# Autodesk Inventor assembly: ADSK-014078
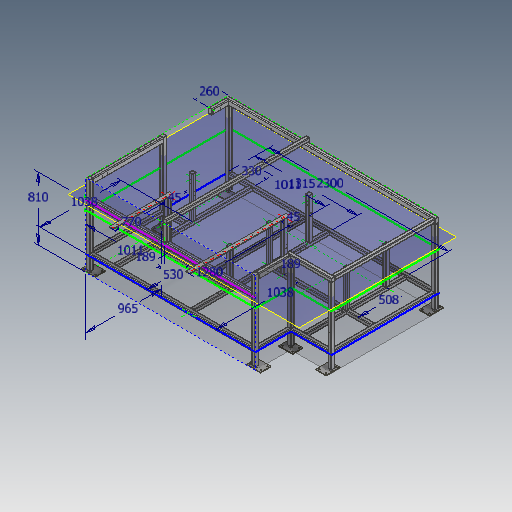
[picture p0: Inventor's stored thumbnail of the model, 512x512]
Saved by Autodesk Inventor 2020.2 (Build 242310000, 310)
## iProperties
_SolveAssemblyDoc: Frame Generator Solve Assembly
_Version: 15.0.0
Created: 2019-10
Part Number: ADSK-014078
Document SubType Name: Assembly
Designer: lutzd
Mass: 3.88702e+07 g
Surface Area: 332354 cm^2
Volume: 4.9579e+06 cm^3
Density: 7.84006 g/cm^3
VLDS_Profile: Default Assembly
VLDS_TimeStamp: 2016-07-29
VLDS_FailCnt: 0
VLDS_AcceptCnt: 0
Dimensions: 2090,9x1100x2753,9 mm
Mass: 38870,239 kg
DocNumber: ADSK-014078
Folder: 01 - Themengebiete\Simplification\01 - Packaging machine\
VDS_Category: 3D Komponenten
VDS_NumSchm: Autodesk
Title: base frame
Author: lutzd
Revision Number: -
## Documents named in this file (5)
- D:\07 - DEMODATEN\OTX 2019 - Dataset - UPDATE - Dez2019\Designs\07-Packing machine\ADSK-014078.iam
- D:\07 - DEMODATEN\OTX 2019 - Dataset - UPDATE - Dez2019\Designs\07-Packing machine\Parts\ADSK-014077.ipt
- D:\07 - DEMODATEN\OTX 2019 - Dataset - UPDATE - Dez2019\Designs\07-Packing machine\ADSK-014078\Frame\ADSK-014079.iam
- D:\07 - DEMODATEN\OTX 2019 - Dataset - UPDATE - Dez2019\Designs\07-Packing machine\Parts\ADSK-011287.ipt
- D:\07 - DEMODATEN\OTX 2019 - Dataset - UPDATE - Dez2019\Designs\07-Packing machine\Parts\ADSK-011288.ipt
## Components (16 placed, 4 different names)
1. ADSK-014077:1 — Fluchtend:5, Fluchtend:6, Fluchtend:7, Fluchtend:8, Fluchtend:9, Fluchtend:10, Fluchtend:11
2. ADSK-014079:1 [sub-assembly] — Passend:25, Passend:26, Passend:44, Passend:51, Passend:52, Passend:53, Passend:60, Passend:61, Passend:68, Passend:69
3. ADSK-011287:5 — Passend:37, Passend:39, Passend:40, Fluchtend:3, Fluchtend:6
4. ADSK-011288:5 — Passend:25, Passend:37, Passend:39, Passend:40
5. ADSK-011287:6 — Passend:34, Passend:35, Passend:36, Fluchtend:7
6. ADSK-011288:6 — Passend:26, Passend:34, Passend:35, Passend:36
7. ADSK-011287:7 — Passend:53, Fluchtend:1, Fluchtend:2, Fluchtend:11
8. ADSK-011288:7 — Passend:44
9. ADSK-011287:8 — Fluchtend:1, Fluchtend:3, Fluchtend:5
10. ADSK-011288:8 — Passend:51
11. ADSK-011287:9 — Fluchtend:2, Fluchtend:10
12. ADSK-011288:9 — Passend:52
13. ADSK-011287:11 — Fluchtend:8
14. ADSK-011288:11 — Passend:60, Passend:61
15. ADSK-011287:13 — Fluchtend:9, Passend:69
16. ADSK-011288:13 — Passend:68
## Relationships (26: Mate 16, Flush 10)
- Passend:25 [Mate]: ADSK-014079:1 ↔ ADSK-011288:5
- Passend:26 [Mate]: ADSK-014079:1 ↔ ADSK-011288:6
- Passend:34 [Mate]: ADSK-011287:6 ↔ ADSK-011288:6
- Passend:35 [Mate]: ADSK-011287:6 ↔ ADSK-011288:6
- Passend:36 [Mate]: ADSK-011287:6 ↔ ADSK-011288:6
- Passend:37 [Mate]: ADSK-011287:5 ↔ ADSK-011288:5
- Passend:39 [Mate]: ADSK-011287:5 ↔ ADSK-011288:5
- Passend:40 [Mate]: ADSK-011287:5 ↔ ADSK-011288:5
- Passend:44 [Mate]: ADSK-014079:1 ↔ ADSK-011288:7
- Passend:51 [Mate]: ADSK-014079:1 ↔ ADSK-011288:8
- Passend:52 [Mate]: ADSK-014079:1 ↔ ADSK-011288:9
- Passend:53 [Mate]: ADSK-014079:1 ↔ ADSK-011287:7
- Fluchtend:1 [Flush]: ADSK-011287:7 ↔ ADSK-011287:8
- Fluchtend:2 [Flush]: ADSK-011287:7 ↔ ADSK-011287:9
- Passend:60 [Mate]: ADSK-014079:1 ↔ ADSK-011288:11
- Passend:61 [Mate]: ADSK-014079:1 ↔ ADSK-011288:11
- Fluchtend:3 [Flush]: ADSK-011287:5 ↔ ADSK-011287:8
- Passend:68 [Mate]: ADSK-014079:1 ↔ ADSK-011288:13
- Fluchtend:5 [Flush]: ADSK-014077:1 ↔ ADSK-011287:8
- Fluchtend:6 [Flush]: ADSK-014077:1 ↔ ADSK-011287:5
- Fluchtend:7 [Flush]: ADSK-014077:1 ↔ ADSK-011287:6
- Fluchtend:8 [Flush]: ADSK-014077:1 ↔ ADSK-011287:11
- Fluchtend:9 [Flush]: ADSK-014077:1 ↔ ADSK-011287:13
- Fluchtend:10 [Flush]: ADSK-014077:1 ↔ ADSK-011287:9
- Fluchtend:11 [Flush]: ADSK-014077:1 ↔ ADSK-011287:7
- Passend:69 [Mate]: ADSK-014079:1 ↔ ADSK-011287:13
## Named parameters: d51_d44 = 0, d52_d45 = 0, d53_d46 = 0, d55_d50 = 45 mm, d56_d47 = 0, d57_d49 = 0, d58_d50 = 45 mm, d59_d47 = 0, d60_d49 = 0, d70_d50 = 45 mm, d71_d47 = 0, d72_d49 = 0, d78_d50 = 45 mm, d79_d47 = 0, d80_d49 = 0
